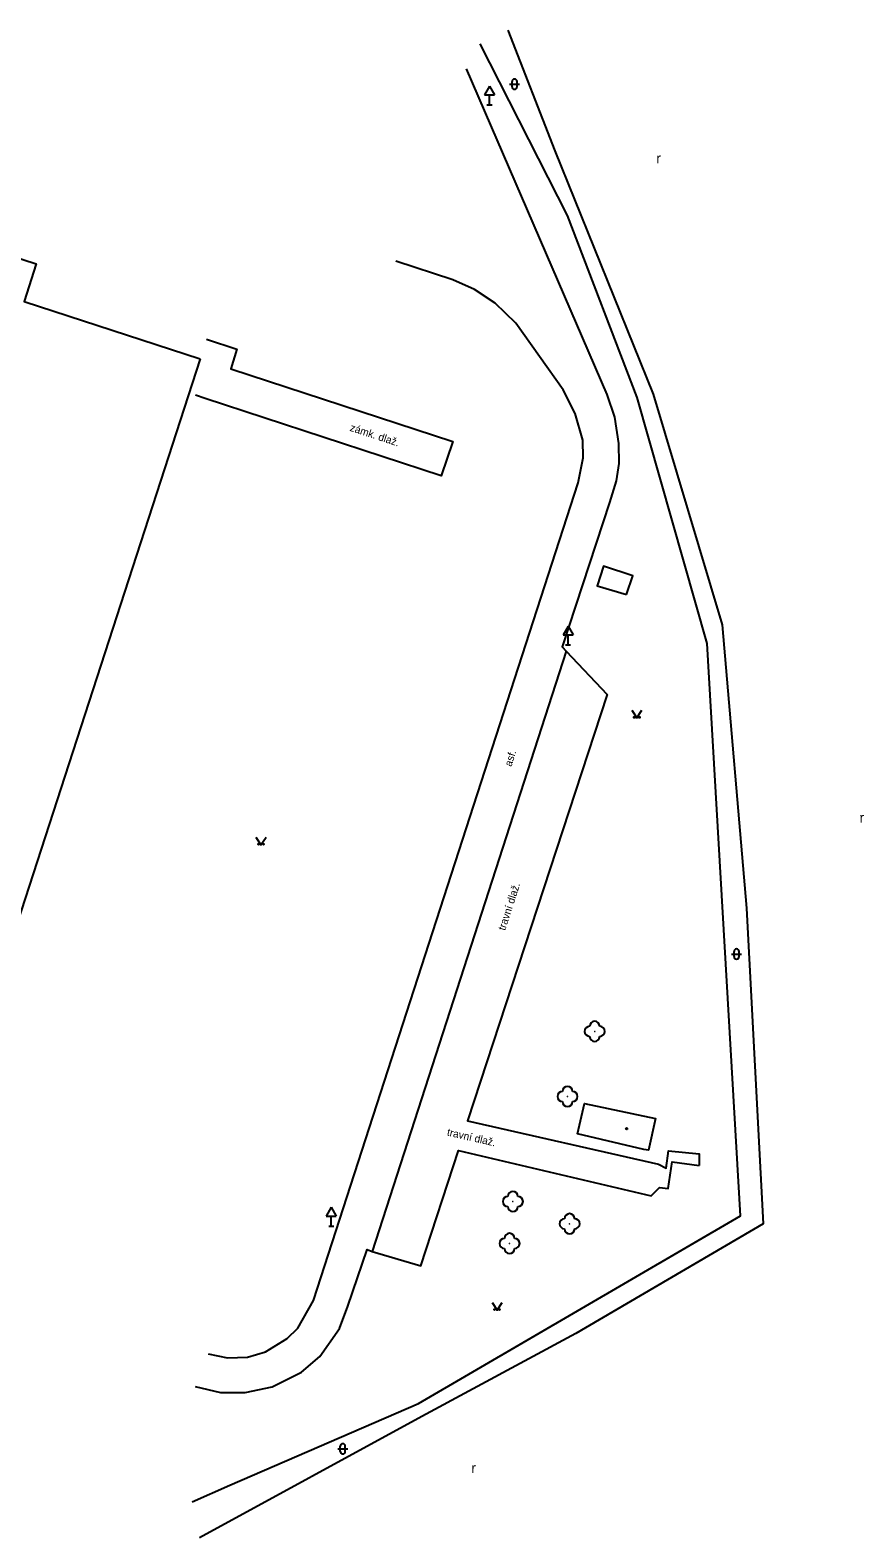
# Model space of a CAD drawing. Extents: x -762421 to -761280, y -1155002 to -1154211.
# Drawn here: x -761760.3 to -761677.7, y -1154360.9 to -1154211.5 of the extents above; entities that cross this region are included whole.
import ezdxf

# ---------------------------------------------------------------- set-up
doc = ezdxf.new("R2010")
doc.units = 0
for name, color, linetype in [('Vrstva 10', 7, 'Continuous'), ('Vrstva 11', 7, 'Continuous'), ('Vrstva 14', 7, 'Continuous'), ('Vrstva 3', 7, 'Continuous'), ('Vrstva 4', 7, 'Continuous'), ('Vrstva 5', 7, 'Continuous'), ('Vrstva 8', 7, 'Continuous'), ('Vrstva 9', 7, 'Continuous')]:
    doc.layers.add(name, color=color, linetype=linetype)

msp = doc.modelspace()

# ---------------------------------------------------------------- linework, layer by layer
at = {"layer": 'Vrstva 10'}
for points in [[(-761717.1, -1154215.32), (-761703.17, -1154247.56), (-761702.43, -1154249.83), (-761702.01, -1154252.42), (-761702, -1154254.42), (-761702.26, -1154256.13), (-761702.9, -1154258.27), (-761707.6, -1154272.57), (-761707.2, -1154273.02)], [(-761742.68, -1154342.63), (-761740.77, -1154343.03), (-761738.76, -1154342.95), (-761736.98, -1154342.42), (-761734.83, -1154341.09), (-761733.79, -1154340.09), (-761732.23, -1154337.34), (-761706.03, -1154256.33), (-761705.51, -1154253.84), (-761705.57, -1154252.11), (-761706.32, -1154249.45), (-761707.5, -1154247.12), (-761712.19, -1154240.51), (-761714.23, -1154238.53), (-761716.28, -1154237.16), (-761718.43, -1154236.2), (-761724.07, -1154234.37)], [(-761742.82, -1154242.11), (-761739.83, -1154243.07), (-761740.44, -1154245.02), (-761718.43, -1154252.22), (-761719.6, -1154255.63), (-761742.96, -1154247.96), (-761743.92, -1154247.63)], [(-761707.2, -1154273.02), (-761726.43, -1154332.48)], [(-761707.2, -1154273.02), (-761703.15, -1154277.3), (-761716.97, -1154319.55), (-761698.06, -1154323.83), (-761697.3, -1154324.23), (-761697.06, -1154322.5), (-761694.02, -1154322.81), (-761694.03, -1154323.95)], [(-761726.43, -1154332.48), (-761721.59, -1154333.9), (-761717.87, -1154322.46), (-761698.8, -1154326.97), (-761697.97, -1154326.14), (-761697.09, -1154326.25), (-761696.72, -1154323.59), (-761694.03, -1154323.95)], [(-761743.96, -1154345.87), (-761741.45, -1154346.45), (-761739.01, -1154346.44), (-761736.33, -1154345.9), (-761733.43, -1154344.44), (-761731.62, -1154342.87), (-761729.66, -1154340.11), (-761728.84, -1154337.91), (-761726.92, -1154332.29), (-761726.43, -1154332.48)]]:
    msp.add_lwpolyline(points, dxfattribs=at)
at = {"layer": 'Vrstva 11'}
msp.add_lwpolyline([(-761712.98, -1154211.48), (-761708.34, -1154223.44), (-761698.57, -1154247.54), (-761691.76, -1154270.41), (-761689.33, -1154298.48), (-761687.7, -1154329.75), (-761706.24, -1154340.59), (-761721.49, -1154348.84), (-761743.53, -1154360.85)], dxfattribs=at)
for centre in [(-761704.38, -1154310.67), (-761707.07, -1154317.13), (-761712.48, -1154327.53), (-761706.86, -1154329.73), (-761712.81, -1154331.68)]:
    msp.add_circle(centre, 0.0005, dxfattribs=at)
for centre, start, end in [((-761704.88, -1154310.67), 89.99999, 269.99999), ((-761704.38, -1154310.17), 0, 179.99999), ((-761703.88, -1154310.67), 270, 89.99999), ((-761704.38, -1154311.17), 179.99999, 359.99999), ((-761707.07, -1154316.63), 0, 179.99999), ((-761707.57, -1154317.13), 89.99999, 269.99999), ((-761707.07, -1154317.63), 179.99999, 359.99999), ((-761706.57, -1154317.13), 270, 89.99999), ((-761712.48, -1154327.03), 0, 179.99999), ((-761712.98, -1154327.53), 89.99999, 269.99999), ((-761712.48, -1154328.03), 179.99999, 359.99999), ((-761711.98, -1154327.53), 270, 89.99999), ((-761707.36, -1154329.73), 89.99999, 269.99999), ((-761706.86, -1154329.23), 0, 179.99999), ((-761706.36, -1154329.73), 270, 89.99999), ((-761713.31, -1154331.68), 89.99999, 269.99999), ((-761712.81, -1154331.18), 0, 179.99999), ((-761712.31, -1154331.68), 270, 89.99999), ((-761706.86, -1154330.23), 179.99999, 359.99999), ((-761712.81, -1154332.18), 179.99999, 359.99999)]:
    msp.add_arc(centre, 0.5, start, end, dxfattribs=at)
at = {"layer": 'Vrstva 3'}
for p, q in [((-761712.82, -1154216.83), (-761711.82, -1154216.83)), ((-761712.57, -1154217.08), (-761712.57, -1154216.58)), ((-761712.07, -1154217.08), (-761712.07, -1154216.58)), ((-761690.57, -1154303.26), (-761690.57, -1154302.76)), ((-761690.07, -1154303.26), (-761690.07, -1154302.76)), ((-761690.82, -1154303.01), (-761689.82, -1154303.01)), ((-761729.84, -1154352.03), (-761728.84, -1154352.03)), ((-761729.59, -1154352.28), (-761729.59, -1154351.78)), ((-761729.09, -1154352.28), (-761729.09, -1154351.78))]:
    msp.add_line(p, q, dxfattribs=at)
for points in [[(-761700.7, -1154278.86), (-761700.2, -1154279.61), (-761699.7, -1154278.86)], [(-761737.94, -1154291.44), (-761737.44, -1154292.19), (-761736.94, -1154291.44)], [(-761714.55, -1154337.53), (-761714.05, -1154338.28), (-761713.55, -1154337.53)]]:
    msp.add_lwpolyline(points, dxfattribs=at)
for centre in [(-761700.45, -1154279.56), (-761699.95, -1154279.56), (-761737.69, -1154292.14), (-761737.19, -1154292.14), (-761714.3, -1154338.23), (-761713.8, -1154338.23)]:
    msp.add_circle(centre, 0.05, dxfattribs=at)
for centre, start, end in [((-761712.32, -1154216.58), 0, 179.99999), ((-761712.32, -1154217.08), 179.99999, 359.99999), ((-761690.32, -1154302.76), 0, 179.99999), ((-761690.32, -1154303.26), 179.99999, 359.99999), ((-761729.34, -1154351.78), 0, 179.99999), ((-761729.34, -1154352.28), 179.99999, 359.99999)]:
    msp.add_arc(centre, 0.25, start, end, dxfattribs=at)
at = {"layer": 'Vrstva 4'}
msp.add_lwpolyline([(-761699.5, -1154322.38), (-761706.08, -1154320.82), (-761705.39, -1154317.81), (-761698.34, -1154319.3), (-761699.06, -1154322.44), (-761699.5, -1154322.38)], dxfattribs=at)
at = {"layer": 'Vrstva 5'}
msp.add_lwpolyline([(-761743.45, -1154244.04), (-761771.46, -1154330.3), (-761780.58, -1154327.33), (-761780.87, -1154328.2), (-761782.68, -1154327.61), (-761782.4, -1154326.73), (-761823.92, -1154313.2), (-761816.49, -1154290.34), (-761816.2, -1154290.44), (-761795.91, -1154227.09), (-761783.28, -1154231.2), (-761782.05, -1154227.36), (-761759.7, -1154234.62), (-761760.89, -1154238.37), (-761743.45, -1154244.04)], dxfattribs=at)
at = {"layer": 'Vrstva 8'}
msp.add_circle((-761701.21, -1154320.31), 0.0875, dxfattribs=at)
at = {"layer": 'Vrstva 9'}
for p, q in [((-761714.8, -1154217.014), (-761715.3, -1154217.88)), ((-761714.8, -1154217.014), (-761714.3, -1154217.88)), ((-761715.3, -1154217.88), (-761714.3, -1154217.88)), ((-761715.05, -1154218.88), (-761714.55, -1154218.88)), ((-761714.8, -1154218.88), (-761714.8, -1154217.88)), ((-761707.01, -1154270.524), (-761707.51, -1154271.39)), ((-761707.51, -1154271.39), (-761706.51, -1154271.39)), ((-761707.01, -1154270.524), (-761706.51, -1154271.39)), ((-761707.01, -1154272.39), (-761707.01, -1154271.39)), ((-761707.26, -1154272.39), (-761706.76, -1154272.39)), ((-761730.48, -1154328.104), (-761730.98, -1154328.97)), ((-761730.48, -1154328.104), (-761729.98, -1154328.97)), ((-761730.98, -1154328.97), (-761729.98, -1154328.97)), ((-761730.48, -1154329.97), (-761730.48, -1154328.97)), ((-761730.73, -1154329.97), (-761730.23, -1154329.97))]:
    msp.add_line(p, q, dxfattribs=at)
for points in [[(-761740.54, -1154355.63), (-761721.82, -1154347.54), (-761689.95, -1154328.94), (-761693.23, -1154272.25), (-761700.18, -1154247.89), (-761707.06, -1154229.83), (-761715.74, -1154212.84)], [(-761701.24, -1154267.38), (-761700.59, -1154265.54), (-761703.5, -1154264.59), (-761704.13, -1154266.52), (-761701.24, -1154267.38)], [(-761744.24, -1154357.28), (-761740.54, -1154355.63)]]:
    msp.add_lwpolyline(points, dxfattribs=at)

# ---------------------------------------------------------------- texts
at = {"layer": 'Vrstva 14'}
for s, rotation, p in [('zámk. dlaž.', 341.88584, (-761728.69, -1154251.16)), ('asf.', 72.07829, (-761712.63, -1154284.49)), ('travní dlaž.', 72.07832, (-761713.26, -1154300.74)), ('travní dlaž.', 347.24896, (-761719.06, -1154320.99))]:
    msp.add_text(s, height=0.75, rotation=rotation, dxfattribs=at).set_placement(p)
at = {"layer": 'Vrstva 3'}
for p in [(-761698.278, -1154224.672), (-761678.138, -1154290.002), (-761716.598, -1154354.422)]:
    msp.add_text('r', height=1, dxfattribs=at).set_placement(p)

doc.saveas('drawing.dxf')
